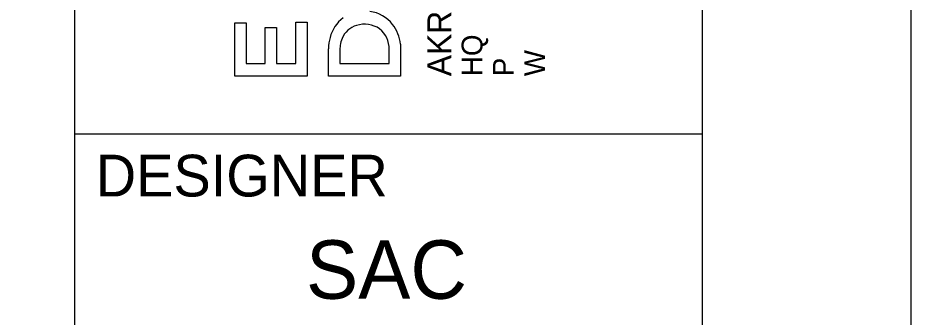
# Model space of a CAD drawing. Extents: x -0.2 to 34, y -0.5 to 22.
# Drawn here: x 31.864 to 34, y 2.061 to 2.778 of the extents above; entities that cross this region are included whole.
import ezdxf

# ---------------------------------------------------------------- set-up
doc = ezdxf.new("R2010")
doc.units = 0
for name, color, linetype in [('SH_Border', 7, 'Continuous'), ('SH_Cut_Line', 7, 'Continuous'), ('SH_Data', 7, 'Continuous')]:
    doc.layers.add(name, color=color, linetype=linetype)

msp = doc.modelspace()

# ---------------------------------------------------------------- linework, layer by layer
at = {"layer": 'SH_Border'}
for p, q in [((32, 0.5), (32, 21.5)), ((32, 2.5), (33.5, 2.5))]:
    msp.add_line(p, q, dxfattribs=at)
msp.add_lwpolyline([(1.5, 21.5), (33.5, 21.5), (33.5, 0.5), (1.5, 0.5)], close=True, dxfattribs=at)
at = {"layer": 'SH_Cut_Line'}
msp.add_lwpolyline([(0, 0), (34, 0), (34, 22), (0, 22)], close=True, dxfattribs=at)
at = {"layer": 'SH_Data'}
for p, q in [((32.383, 2.6379), (32.383, 2.766)), ((32.383, 2.766), (32.4101, 2.766)), ((32.4101, 2.766), (32.4101, 2.6683)), ((32.5286, 2.6683), (32.5286, 2.7672)), ((32.5286, 2.7672), (32.5557, 2.7672)), ((32.5557, 2.7672), (32.5557, 2.6379)), ((32.455, 2.6683), (32.455, 2.7549)), ((32.455, 2.7549), (32.4822, 2.7549)), ((32.4822, 2.7549), (32.4822, 2.6683)), ((32.7785, 2.715), (32.7792, 2.7021)), ((32.6064, 2.638), (32.6064, 2.704)), ((32.6347, 2.7118), (32.6341, 2.7023)), ((32.6341, 2.7023), (32.6341, 2.6684)), ((32.7515, 2.6683), (32.7515, 2.7024)), ((32.7792, 2.7021), (32.7792, 2.638)), ((32.4101, 2.6683), (32.455, 2.6683)), ((32.4822, 2.6683), (32.5286, 2.6683)), ((32.6341, 2.6684), (32.7515, 2.6683)), ((32.5557, 2.6379), (32.383, 2.6379)), ((32.7792, 2.638), (32.6064, 2.638))]:
    msp.add_line(p, q, dxfattribs=at)
msp.add_lwpolyline([(32.383, 2.6379), (32.383, 2.766), (32.4101, 2.766), (32.4101, 2.6683), (32.455, 2.6683), (32.455, 2.7549), (32.4822, 2.7549), (32.4822, 2.6683), (32.5286, 2.6683), (32.5286, 2.7672), (32.5557, 2.7672), (32.5557, 2.6379)], close=True, dxfattribs=at)
for points in [[(32.7785, 2.715), (32.7792, 2.7021), (32.7792, 2.638), (32.6064, 2.638)], [(32.6064, 2.638), (32.6064, 2.704)], [(32.6347, 2.7118), (32.6341, 2.7023), (32.6341, 2.6684), (32.7515, 2.6683), (32.7515, 2.7024)]]:
    msp.add_lwpolyline(points, dxfattribs=at)
for centre, radius, start, end in [((32.6939, 2.7089), 0.0865, 127.2362, 165.148), ((32.6939, 2.7089), 0.0865, 127.2362, 165.148), ((32.6946, 2.7113), 0.0827, 37.8521, 82.402), ((32.6946, 2.7113), 0.0827, 37.8521, 82.402), ((32.6889, 2.7078), 0.054, 106.1881, 157.3861), ((32.6889, 2.7078), 0.054, 106.1881, 157.3861), ((32.6928, 2.6986), 0.0639, 55.6727, 107.2093), ((32.6928, 2.6986), 0.0639, 55.6727, 107.2093), ((32.6859, 2.7057), 0.0931, 5.7333, 37.304), ((32.6859, 2.7057), 0.0931, 5.7333, 37.304), ((32.6929, 2.705), 0.0587, 357.4662, 52.2665), ((32.6929, 2.705), 0.0587, 357.4662, 52.2665), ((32.7143, 2.7028), 0.1078, 164.7861, 179.3704), ((32.7143, 2.7028), 0.1078, 164.7861, 179.3704), ((32.6983, 2.7039), 0.0641, 157.3571, 172.9275), ((32.6983, 2.7039), 0.0641, 157.3571, 172.9275)]:
    msp.add_arc(centre, radius, start, end, dxfattribs=at)

# ---------------------------------------------------------------- texts
for s, height, p in [('AKRON / CLEVELAND / COLUMBUS', 0.056969, (32.9001, 2.638)), ('HQ ', 0.04985, (32.9749, 2.638)), ('W', 0.0498, (33.1244, 2.638)), ('P', 0.0498, (33.0497, 2.638))]:
    msp.add_text(s, height=height, rotation=90, dxfattribs=at).set_placement(p)
for s, height, p in [('DESIGNER', 0.1, (32.05, 2.35)), ('SAC', 0.14, (32.5528, 2.105))]:
    msp.add_text(s, height=height, dxfattribs=at).set_placement(p)

doc.saveas('drawing.dxf')
